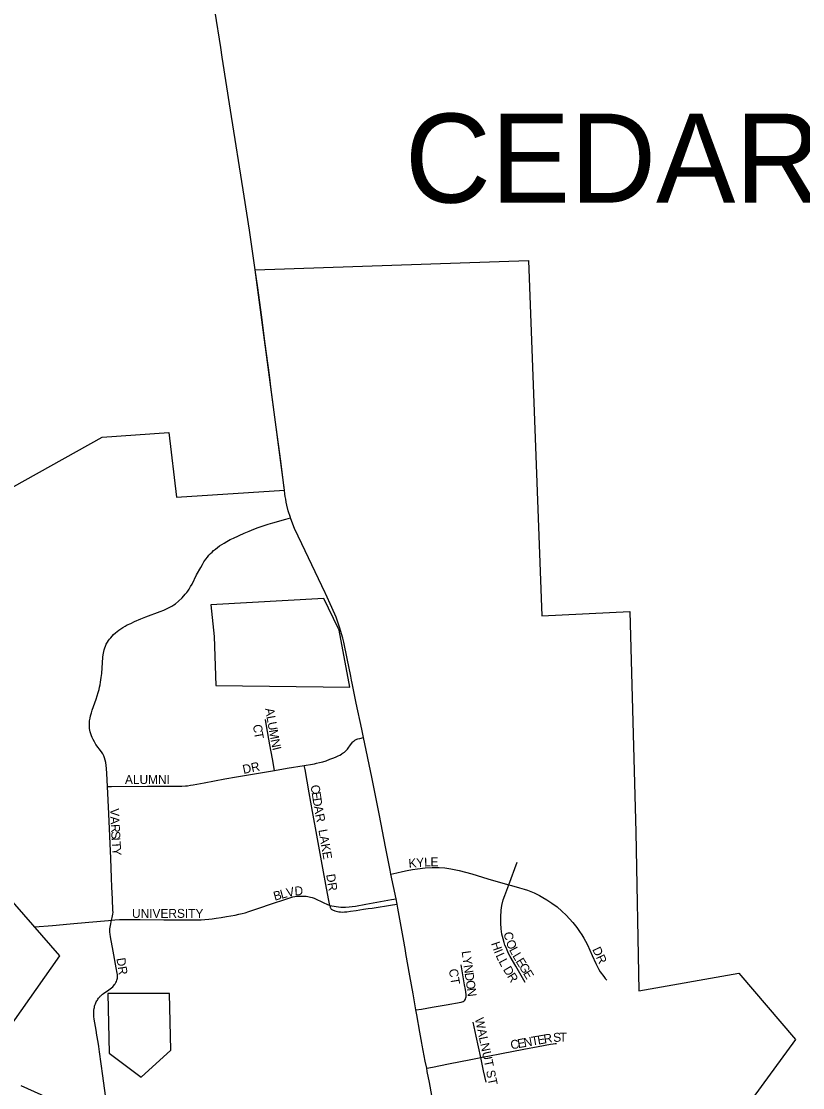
# Model space of a CAD drawing. Extents: x -19.5 to 44.1, y 0 to 22.
# Drawn here: x -18.279 to -17.447, y 4.256 to 5.391 of the extents above; entities that cross this region are included whole.
import ezdxf

# ---------------------------------------------------------------- set-up
doc = ezdxf.new("R2010")
doc.units = 0
for name, color, linetype in [('GM_X_City_Street', 7, 'Continuous'), ('GM_X_City_Street_Text', 7, 'Continuous'), ('GM_X_Corporation', 7, 'Continuous'), ('GM_X_Corporation_Text', 7, 'Continuous'), ('GM_X_State_Route', 7, 'Continuous')]:
    doc.layers.add(name, color=color, linetype=linetype)

msp = doc.modelspace()

# ---------------------------------------------------------------- linework, layer by layer
at = {"layer": 'GM_X_City_Street'}
for points in [[(-18.1868, 4.5765), (-18.1876, 4.5904), (-18.188, 4.5957), (-18.1883, 4.5991), (-18.1887, 4.6023), (-18.1893, 4.6048), (-18.19, 4.6073), (-18.1907, 4.6093), (-18.1918, 4.6113), (-18.1932, 4.6135), (-18.1992, 4.6214), (-18.2008, 4.6241), (-18.2022, 4.6267), (-18.2031, 4.6288), (-18.2039, 4.6306), (-18.2046, 4.6328), (-18.2051, 4.6347), (-18.2058, 4.6382), (-18.206, 4.6403), (-18.2061, 4.6418), (-18.206, 4.6443), (-18.2059, 4.6466), (-18.2054, 4.6495), (-18.2049, 4.652), (-18.204, 4.6551), (-18.2031, 4.6579), (-18.199, 4.6696), (-18.1977, 4.6733), (-18.1966, 4.6767), (-18.1958, 4.6797), (-18.1952, 4.6822), (-18.1947, 4.6849), (-18.1942, 4.6877), (-18.1935, 4.6926), (-18.193, 4.697), (-18.1917, 4.7144), (-18.1915, 4.7166), (-18.1911, 4.7186), (-18.1908, 4.7204), (-18.1903, 4.7222), (-18.1896, 4.7243), (-18.1889, 4.7261), (-18.1881, 4.728), (-18.1869, 4.7301), (-18.1857, 4.7319), (-18.1846, 4.7334), (-18.1834, 4.7349), (-18.1819, 4.7367), (-18.1804, 4.7383), (-18.1784, 4.7401), (-18.1766, 4.7416), (-18.1746, 4.7432), (-18.1726, 4.7445), (-18.1705, 4.7459), (-18.1681, 4.7474), (-18.1657, 4.7486), (-18.162, 4.7503), (-18.1579, 4.7522), (-18.1513, 4.755), (-18.1459, 4.7573), (-18.1308, 4.7629), (-18.1268, 4.7645), (-18.1232, 4.766), (-18.1203, 4.7674), (-18.1182, 4.7686), (-18.116, 4.77), (-18.1145, 4.7711), (-18.1111, 4.7739), (-18.1074, 4.7774), (-18.104, 4.7812), (-18.1025, 4.783), (-18.1014, 4.7845), (-18.1, 4.7867), (-18.0983, 4.7895), (-18.0968, 4.792), (-18.092, 4.8019), (-18.0875, 4.8099), (-18.0858, 4.8131), (-18.0842, 4.8159), (-18.0821, 4.8187), (-18.0804, 4.8209), (-18.0789, 4.8227), (-18.0772, 4.8245), (-18.0755, 4.8261), (-18.0738, 4.8277), (-18.0718, 4.8293), (-18.0696, 4.8312), (-18.0674, 4.8328), (-18.0651, 4.8343), (-18.0626, 4.8358), (-18.0599, 4.8374), (-18.0561, 4.8394), (-18.0526, 4.841), (-18.0414, 4.8462), (-18.0361, 4.8484), (-18.0311, 4.8504), (-18.0263, 4.8523), (-18.0212, 4.8541), (-18.0156, 4.8559), (-18.0106, 4.8574), (-17.997, 4.8612), (-17.9919, 4.8626)], [(-18.0089, 4.5938), (-18.0112, 4.6059), (-18.014, 4.6211), (-18.0176, 4.6412), (-18.0187, 4.648)], [(-17.9773, 4.599), (-17.9685, 4.6004), (-17.9663, 4.6008), (-17.9642, 4.6013), (-17.961, 4.602), (-17.9576, 4.603), (-17.9541, 4.6041), (-17.9499, 4.6056), (-17.9457, 4.6071), (-17.9432, 4.6081), (-17.9411, 4.6091), (-17.9393, 4.6101), (-17.9378, 4.611), (-17.9368, 4.6116), (-17.9359, 4.6123), (-17.9346, 4.6132), (-17.9333, 4.6144), (-17.9323, 4.6154), (-17.9314, 4.6163), (-17.9306, 4.6173), (-17.9281, 4.6209), (-17.9267, 4.6227), (-17.9259, 4.6238), (-17.9251, 4.6246), (-17.9242, 4.6254), (-17.9233, 4.626), (-17.9222, 4.6266), (-17.9212, 4.627), (-17.9202, 4.6273), (-17.9182, 4.6278), (-17.9141, 4.6288)], [(-18.0089, 4.5938), (-17.9954, 4.596), (-17.9773, 4.599)], [(-17.9502, 4.4501), (-17.9512, 4.4553), (-17.9536, 4.4683), (-17.9575, 4.4896), (-17.964, 4.5247), (-17.9686, 4.55), (-17.972, 4.5697), (-17.9765, 4.5948), (-17.9773, 4.599)], [(-18.1868, 4.5765), (-18.1826, 4.5766), (-18.1441, 4.5769), (-18.1075, 4.5771), (-18.1039, 4.5773), (-18.1017, 4.5775), (-18.0984, 4.5779), (-18.0955, 4.5784), (-18.0837, 4.5805), (-18.0617, 4.5847), (-18.0493, 4.5869), (-18.0345, 4.5895), (-18.0089, 4.5938)], [(-18.1824, 4.4343), (-18.1818, 4.437), (-18.1811, 4.4407), (-18.1809, 4.4427), (-18.181, 4.4446), (-18.1814, 4.457), (-18.1821, 4.4694), (-18.1824, 4.4793), (-18.1834, 4.4998), (-18.1855, 4.5476), (-18.1868, 4.5765)], [(-17.7596, 4.4721), (-17.7507, 4.4962)], [(-17.885, 4.4833), (-17.8786, 4.4848), (-17.8728, 4.486), (-17.8676, 4.4871), (-17.8622, 4.4882), (-17.8566, 4.489), (-17.8486, 4.49), (-17.8412, 4.4904), (-17.8337, 4.4904), (-17.8275, 4.4899), (-17.8214, 4.4891), (-17.8122, 4.4871), (-17.799, 4.4836), (-17.7818, 4.4784), (-17.771, 4.4752), (-17.7596, 4.4721)], [(-17.742, 4.368), (-17.7522, 4.3853), (-17.7579, 4.3957), (-17.7597, 4.399), (-17.7612, 4.4024), (-17.7625, 4.4053), (-17.7636, 4.4078), (-17.7645, 4.4107), (-17.7656, 4.4143), (-17.7668, 4.4195), (-17.7676, 4.425), (-17.768, 4.4312), (-17.768, 4.4375), (-17.7675, 4.4449), (-17.7668, 4.4498), (-17.7654, 4.4559), (-17.7639, 4.4606), (-17.7596, 4.4721)], [(-17.7596, 4.4721), (-17.7567, 4.4712), (-17.7483, 4.4689), (-17.743, 4.4673), (-17.7395, 4.4661), (-17.736, 4.4648), (-17.7325, 4.4633), (-17.7297, 4.4619), (-17.727, 4.4606), (-17.7233, 4.4586), (-17.7191, 4.456), (-17.7137, 4.4524), (-17.7082, 4.4484), (-17.703, 4.444), (-17.6985, 4.4396), (-17.6915, 4.4318), (-17.6872, 4.4264), (-17.6843, 4.4224), (-17.6819, 4.4187), (-17.6797, 4.415), (-17.678, 4.4119), (-17.6759, 4.4079), (-17.6706, 4.3967), (-17.6667, 4.3883), (-17.6653, 4.3853), (-17.6635, 4.3817), (-17.6621, 4.3793), (-17.6609, 4.3775), (-17.6599, 4.376), (-17.6585, 4.3742), (-17.657, 4.3724), (-17.6553, 4.3705)], [(-18.1824, 4.4343), (-18.1791, 4.4346), (-18.1741, 4.4349), (-18.1669, 4.4352), (-18.1519, 4.435), (-18.1269, 4.4348), (-18.1084, 4.4348), (-18.0966, 4.4347), (-18.0872, 4.4348), (-18.0833, 4.4351), (-18.0788, 4.4355), (-18.0753, 4.4359), (-18.0711, 4.4365), (-18.0657, 4.4372), (-18.06, 4.4381), (-18.0508, 4.4398), (-18.047, 4.4406), (-18.0435, 4.4414), (-18.0402, 4.4423), (-18.0363, 4.4435), (-18.0269, 4.4468), (-18.011, 4.4522), (-17.9981, 4.4565), (-17.9916, 4.4585), (-17.9896, 4.459), (-17.9875, 4.4595), (-17.9855, 4.4597), (-17.9833, 4.4599), (-17.9808, 4.46), (-17.9784, 4.4599), (-17.9766, 4.4598), (-17.9751, 4.4597), (-17.9735, 4.4595), (-17.972, 4.4592), (-17.9706, 4.4589), (-17.9689, 4.4583), (-17.9669, 4.4576), (-17.9566, 4.4529), (-17.9534, 4.4514), (-17.9502, 4.4501)], [(-17.9502, 4.4501), (-17.9434, 4.449), (-17.9408, 4.4486), (-17.9383, 4.4483), (-17.9359, 4.4482), (-17.9333, 4.4482), (-17.9296, 4.4484), (-17.9264, 4.4487), (-17.9228, 4.4492), (-17.9119, 4.4512), (-17.8844, 4.4562), (-17.8796, 4.4571)], [(-17.9502, 4.4501), (-17.9498, 4.4487), (-17.9496, 4.4479), (-17.9494, 4.4474), (-17.9491, 4.4468), (-17.9486, 4.4462), (-17.948, 4.4457), (-17.9471, 4.4452), (-17.9465, 4.4449), (-17.9456, 4.4445), (-17.9448, 4.4442), (-17.9434, 4.4439), (-17.9419, 4.4435), (-17.9404, 4.4433), (-17.9386, 4.4431), (-17.9367, 4.443), (-17.9346, 4.4431), (-17.9321, 4.4433), (-17.9279, 4.4438), (-17.922, 4.4447), (-17.9142, 4.446), (-17.9119, 4.4463), (-17.9091, 4.4467), (-17.9049, 4.4472), (-17.8832, 4.4505), (-17.8785, 4.4512)], [(-18.2642, 4.4273), (-18.2452, 4.4288), (-18.2267, 4.4305), (-18.2068, 4.4321), (-18.1857, 4.434), (-18.1824, 4.4343)], [(-18.1856, 4.2244), (-18.1916, 4.2687), (-18.1953, 4.294), (-18.1961, 4.2997), (-18.1969, 4.3044), (-18.1981, 4.3118), (-18.199, 4.3173), (-18.2009, 4.3289), (-18.2013, 4.3319), (-18.2015, 4.3335), (-18.2015, 4.3349), (-18.2015, 4.3362), (-18.2015, 4.3372), (-18.2013, 4.3386), (-18.201, 4.3403), (-18.2008, 4.3415), (-18.2005, 4.3428), (-18.2002, 4.3437), (-18.1997, 4.3451), (-18.1993, 4.3462), (-18.1988, 4.3473), (-18.1983, 4.3483), (-18.1976, 4.3493), (-18.197, 4.3503), (-18.1963, 4.3512), (-18.1957, 4.3519), (-18.1951, 4.3526), (-18.1945, 4.3533), (-18.1939, 4.3539), (-18.193, 4.3547), (-18.1922, 4.3554), (-18.1911, 4.3561), (-18.1855, 4.36), (-18.1839, 4.3612), (-18.1825, 4.3623), (-18.1812, 4.3635), (-18.1802, 4.3646), (-18.1793, 4.3657), (-18.1786, 4.3667), (-18.1779, 4.3678), (-18.1773, 4.369), (-18.1768, 4.3704), (-18.1765, 4.3715), (-18.1763, 4.3727), (-18.1761, 4.3741), (-18.1761, 4.3754), (-18.1762, 4.3766), (-18.1764, 4.378), (-18.1774, 4.3836), (-18.1807, 4.4013), (-18.1836, 4.4165), (-18.1841, 4.4194), (-18.1842, 4.4214), (-18.1843, 4.4232), (-18.1842, 4.425), (-18.1841, 4.4267), (-18.1837, 4.4285), (-18.1824, 4.4343)], [(-17.8585, 4.3387), (-17.8525, 4.3397), (-17.8413, 4.3416), (-17.8262, 4.3442), (-17.8101, 4.3471), (-17.8091, 4.3474), (-17.808, 4.3478), (-17.807, 4.3485), (-17.8063, 4.3492), (-17.8058, 4.3501), (-17.8055, 4.3508), (-17.8052, 4.3518), (-17.805, 4.3527), (-17.8049, 4.3539), (-17.805, 4.3551), (-17.8058, 4.3606), (-17.8066, 4.3655), (-17.8102, 4.3866)], [(-17.7892, 4.2881), (-17.7942, 4.3107), (-17.7976, 4.3257)], [(-17.7892, 4.2881), (-17.7879, 4.2884), (-17.7818, 4.2895), (-17.7674, 4.2925), (-17.7434, 4.2971), (-17.7284, 4.2999), (-17.7153, 4.3023), (-17.7124, 4.3028), (-17.71, 4.3031), (-17.7087, 4.3031)], [(-17.8469, 4.2768), (-17.8408, 4.278), (-17.8237, 4.2813), (-17.8, 4.2859), (-17.7892, 4.2881)], [(-17.7837, 4.2617), (-17.7863, 4.2739), (-17.7892, 4.2881)]]:
    msp.add_lwpolyline(points, dxfattribs=at)
at = {"layer": 'GM_X_Corporation'}
for points in [[(-18.5208, 4.7654), (-18.1926, 4.9486), (-18.1215, 4.9534), (-18.1135, 4.8846), (-17.9985, 4.8919), (-18.0073, 4.9592), (-18.0296, 5.1266), (-17.7386, 5.1366), (-17.7244, 4.7582), (-17.6307, 4.7629), (-17.6244, 4.528), (-17.6211, 4.3592), (-17.5147, 4.3778), (-17.4542, 4.3072), (-17.5641, 4.1571)], [(-18.3363, 4.2565), (-18.2374, 4.3963), (-18.4104, 4.5945)], [(-18.2502, 4.2453), (-18.2788, 4.258)]]:
    msp.add_lwpolyline(points, dxfattribs=at)
for points in [[(-18.0733, 4.7363), (-18.0714, 4.6841), (-17.9287, 4.6825), (-17.9403, 4.7432), (-17.9413, 4.7453), (-17.9564, 4.7768), (-18.0766, 4.77)], [(-18.1866, 4.3562), (-18.185, 4.2927), (-18.1511, 4.2672), (-18.1192, 4.2959), (-18.1208, 4.3562)]]:
    msp.add_lwpolyline(points, close=True, dxfattribs=at)
at = {"layer": 'GM_X_State_Route'}
for points in [[(-17.9985, 4.8919), (-17.9992, 4.897), (-18.0024, 4.9229), (-18.0073, 4.9592), (-18.0125, 4.9992), (-18.0144, 5.0146), (-18.0188, 5.0478), (-18.023, 5.0786), (-18.0268, 5.1075), (-18.0296, 5.1266), (-18.0356, 5.1688), (-18.0412, 5.2051), (-18.0558, 5.2965), (-18.0646, 5.353), (-18.0662, 5.3634), (-18.0721, 5.4008)], [(-17.9546, 4.7819), (-17.955, 4.7828), (-17.9658, 4.8052), (-17.98, 4.8349), (-17.9876, 4.8513), (-17.9906, 4.8588), (-17.9919, 4.8626), (-17.9921, 4.863), (-17.9943, 4.8701), (-17.9959, 4.8762), (-17.9965, 4.8792), (-17.9971, 4.8826), (-17.9977, 4.8855), (-17.998, 4.8879), (-17.9985, 4.8919)], [(-17.9394, 4.745), (-17.9402, 4.7474), (-17.9435, 4.7567), (-17.9478, 4.767), (-17.9546, 4.7819)], [(-17.9263, 4.6865), (-17.927, 4.6898), (-17.9278, 4.6942), (-17.9317, 4.713), (-17.9353, 4.7302), (-17.9363, 4.7345), (-17.9376, 4.7392), (-17.9394, 4.745)], [(-17.8696, 4.4019), (-17.8721, 4.416), (-17.8777, 4.4472), (-17.8785, 4.4512), (-17.8796, 4.4571), (-17.8822, 4.4703), (-17.885, 4.4833), (-17.8859, 4.4874), (-17.8908, 4.5123), (-17.8973, 4.5459), (-17.9055, 4.5867), (-17.9141, 4.6288), (-17.916, 4.6378), (-17.9219, 4.6655), (-17.9263, 4.6865)], [(-17.8521, 4.3033), (-17.8543, 4.3152), (-17.8576, 4.3334), (-17.8585, 4.3387), (-17.8615, 4.356), (-17.8648, 4.375), (-17.8691, 4.3989), (-17.8696, 4.4019)], [(-17.839, 4.2342), (-17.8415, 4.2477), (-17.8441, 4.2615), (-17.8463, 4.2732), (-17.8469, 4.2768), (-17.8484, 4.2841), (-17.8517, 4.3012), (-17.8521, 4.3033)]]:
    msp.add_lwpolyline(points, dxfattribs=at)

# ---------------------------------------------------------------- texts
at = {"layer": 'GM_X_City_Street_Text'}
for s, rotation, p in [('A', 279.908, (-18.019, 4.6594)), ('L', 279.8845, (-18.0176, 4.6512)), ('U', 279.9108, (-18.0164, 4.6447)), ('C', 276.9865, (-18.0319, 4.6422)), ('T', 280.4616, (-18.0309, 4.6341)), ('M', 279.9025, (-18.015, 4.6365)), ('N', 281.4565, (-18.0132, 4.6263)), ('I', 283.8566, (-18.0115, 4.6177)), ('DR', 11.8817, (-18.0419, 4.59)), ('ALUMNI', 0, (-18.1682, 4.5793)), ('C', 278.6557, (-17.9706, 4.5777)), ('E', 278.6402, (-17.9695, 4.5703)), ('D', 278.6522, (-17.9685, 4.5637)), ('V', 271.2677, (-18.184, 4.5533)), ('A', 279.9815, (-17.9672, 4.5553)), ('A', 272.9364, (-18.1838, 4.5446)), ('R', 282.0249, (-17.9657, 4.5467)), ('R', 273.1641, (-18.1833, 4.5363)), ('LAKE', 279.8648, (-17.9623, 4.5303)), ('S', 273.1919, (-18.1829, 4.5288)), ('I', 273.1483, (-18.1826, 4.5221)), ('T', 273.1919, (-18.1823, 4.5179)), ('Y', 273.1713, (-18.1819, 4.5113)), ('K', 5.0123, (-17.8659, 4.49)), ('Y', 5.04, (-17.8576, 4.4907)), ('L', 1.5578, (-17.8495, 4.4914)), ('E', 0.3825, (-17.8429, 4.4916)), ('DR', 278.9673, (-17.954, 4.4828)), ('B', 15.4383, (-18.0087, 4.455)), ('L', 15.4428, (-18.0015, 4.457)), ('V', 12.9389, (-17.9952, 4.4588)), ('D', 2.4269, (-17.9875, 4.4606)), ('UNIVERSITY', 0, (-18.1607, 4.4368)), ('C', 277.5256, (-17.7648, 4.4213)), ('H', 288.9394, (-17.7785, 4.4096)), ('O', 293.2319, (-17.763, 4.4111)), ('L', 297.5941, (-17.7594, 4.4028)), ('DR', 295.1968, (-17.6709, 4.4032)), ('DR', 278.5367, (-18.1773, 4.3936)), ('L', 278.0297, (-17.8098, 4.4011)), ('Y', 278.043, (-17.8089, 4.3945)), ('I', 292.3828, (-17.7756, 4.4011)), ('L', 295.0927, (-17.7738, 4.3968)), ('L', 298.0764, (-17.7707, 4.3903)), ('L', 300.8426, (-17.756, 4.3964)), ('E', 301.4583, (-17.7526, 4.3905)), ('CT', 279.4564, (-17.8234, 4.3818)), ('N', 278.0467, (-17.8077, 4.3862)), ('D', 301.2319, (-17.766, 4.3818)), ('G', 301.4285, (-17.7491, 4.3849)), ('E', 301.4089, (-17.7447, 4.3777)), ('D', 278.0467, (-17.8066, 4.378)), ('R', 301.4945, (-17.7617, 4.3746)), ('O', 278.0467, (-17.8054, 4.3697)), ('N', 276.9461, (-17.8042, 4.3615)), ('WALNUT ST', 281.9953, (-17.7957, 4.3295)), ('S', 3.7995, (-17.712, 4.3046)), ('T', 0.2459, (-17.7055, 4.3051)), ('C', 10.0811, (-17.7569, 4.2967)), ('E', 10.0507, (-17.7495, 4.298)), ('N', 10.0742, (-17.7429, 4.2992)), ('T', 10.0776, (-17.7347, 4.3007)), ('E', 10.0507, (-17.7282, 4.3018)), ('R', 10.0729, (-17.7216, 4.303))]:
    msp.add_text(s, height=0.00947, rotation=rotation, dxfattribs=at).set_placement(p)
at = {"layer": 'GM_X_Corporation_Text'}
msp.add_text('CEDARVILLE', height=0.0947, rotation=0, dxfattribs=at).set_placement((-17.8701, 5.1982))

doc.saveas('drawing.dxf')
